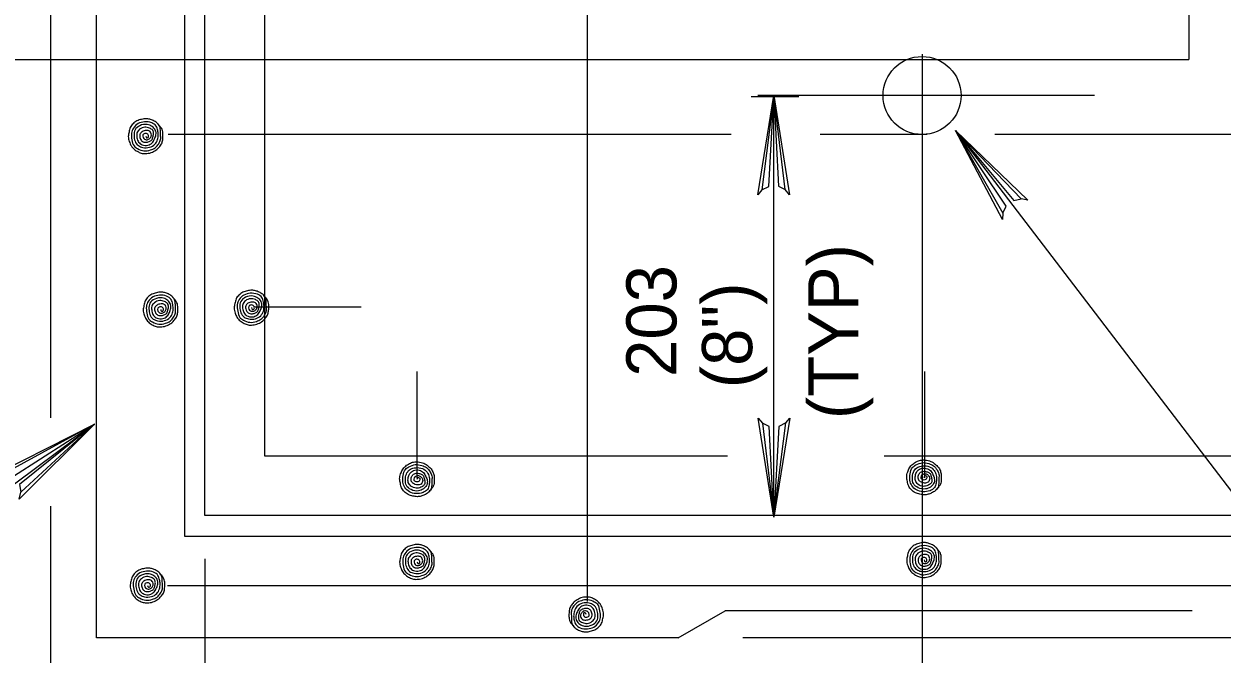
# Model space of a CAD drawing. Extents: x 638455 to 640199, y 298558 to 299152.
# Drawn here: x 638610.5 to 638690.8, y 298927.7 to 298970 of the extents above; entities that cross this region are included whole.
import ezdxf

# ---------------------------------------------------------------- set-up
doc = ezdxf.new("R2010")
doc.units = 0
for name, color, linetype in [('1', 7, 'Continuous'), ('2', 7, 'Continuous'), ('3', 7, 'Continuous')]:
    doc.layers.add(name, color=color, linetype=linetype)

msp = doc.modelspace()

# ---------------------------------------------------------------- linework, layer by layer
at = {"layer": '1'}
msp.add_line((638654.3, 298928.815), (638657.46, 298930.633), dxfattribs=at)
msp.add_lwpolyline([(638609.271, 298939.891), (638609.759, 298939.645), (638615.183, 298943.151), (638609.271, 298939.891), (638608.821, 298939.926), (638615.183, 298943.151), (638610.159, 298939.103), (638610.252, 298938.577), (638615.183, 298943.151), (638610.147, 298938.104), (638610.252, 298938.577)], dxfattribs=at)
at = {"layer": '2'}
for p, q in [((638612.27, 298943.574), (638612.27, 299043.396)), ((638615.328, 298928.815), (638615.328, 299041.293)), ((638648.201, 299038.114), (638648.201, 298931.255)), ((638688.53, 299002.44), (638688.53, 298967.592)), ((638529.296, 298967.592), (638688.53, 298967.592)), ((638670.649, 298967.953), (638670.649, 298905.861)), ((638659.191, 298965.101), (638662.389, 298965.101)), ((638682.211, 298965.179), (638659.644, 298965.179)), ((638660.717, 298936.898), (638660.717, 298965.179)), ((638620.12, 298962.581), (638657.852, 298962.581)), ((638663.822, 298962.581), (638670.987, 298962.581)), ((638672.897, 298962.831), (638713.687, 298909.405)), ((638675.524, 298962.581), (638721.179, 298962.581)), ((638625.946, 298951.012), (638633.07, 298951.012)), ((638636.797, 298946.662), (638636.797, 298939.538)), ((638670.822, 298946.662), (638670.822, 298939.538)), ((638603.045, 298934.093), (638615.183, 298943.151)), ((638657.613, 298940.985), (638626.618, 298940.985)), ((638714.68, 298940.985), (638668.121, 298940.985)), ((638612.27, 298926.637), (638612.27, 298937.652)), ((638622.593, 298934.105), (638622.593, 298879.959)), ((638620.085, 298932.332), (638721.904, 298932.332)), ((638688.753, 298930.633), (638657.46, 298930.633)), ((638654.3, 298928.815), (638615.328, 298928.815)), ((638725.979, 298928.815), (638658.629, 298928.815))]:
    msp.add_line(p, q, dxfattribs=at)
for points in [[(638621.251, 299034.415), (638720.048, 299034.415), (638720.048, 298935.618), (638621.251, 298935.618), (638621.251, 299034.415)], [(638622.593, 299033.135), (638718.705, 299033.135), (638718.705, 298937.023), (638622.593, 298937.023), (638622.593, 299033.135)], [(638626.618, 298940.985), (638626.618, 299029.048)], [(638659.922, 298958.848), (638660.381, 298959.083), (638660.717, 298965.179), (638659.922, 298958.848), (638659.646, 298958.522), (638660.717, 298965.179), (638661.019, 298959.089), (638661.472, 298958.868), (638660.717, 298965.179), (638661.774, 298958.522), (638661.472, 298958.868)], [(638676.07, 298957.296), (638676.293, 298957.761), (638672.897, 298962.831), (638676.07, 298957.296), (638676.041, 298956.87), (638672.897, 298962.831), (638676.799, 298958.146), (638677.296, 298958.244), (638672.897, 298962.831), (638677.743, 298958.152), (638677.296, 298958.244)], [(638661.513, 298943.226), (638661.054, 298942.991), (638660.717, 298936.898), (638661.513, 298943.226), (638661.789, 298943.551), (638660.717, 298936.898), (638660.415, 298942.985), (638659.962, 298943.209), (638660.717, 298936.898), (638659.66, 298943.551), (638659.962, 298943.209)]]:
    msp.add_lwpolyline(points, dxfattribs=at)
msp.add_circle((638670.649, 298965.178), 2.614, dxfattribs=at)
for points in [[(638618.63, 298962.454), (638618.688, 298962.338), (638618.775, 298962.352), (638618.795, 298962.535), (638618.633, 298962.631), (638618.438, 298962.535), (638618.447, 298962.352), (638618.554, 298962.239), (638618.775, 298962.221), (638618.929, 298962.338), (638619.004, 298962.526), (638618.891, 298962.776), (638618.65, 298962.828), (638618.383, 298962.747), (638618.24, 298962.579), (638618.258, 298962.294), (638618.392, 298962.111), (638618.633, 298962.044), (638618.848, 298962.088), (638619.024, 298962.195), (638619.103, 298962.381), (638619.147, 298962.622), (638619.091, 298962.846), (638618.882, 298962.988), (638618.563, 298963.052), (638618.214, 298962.91), (638618.04, 298962.669), (638618.04, 298962.338), (638618.151, 298962.056), (638618.392, 298961.87), (638618.775, 298961.847), (638619.048, 298961.998), (638619.213, 298962.262), (638619.312, 298962.535), (638619.266, 298962.863), (638619.048, 298963.096), (638618.731, 298963.229), (638618.226, 298963.151), (638617.91, 298962.872), (638617.843, 298962.488), (638617.91, 298962.111), (638618.13, 298961.815), (638618.424, 298961.696), (638618.882, 298961.704), (638619.245, 298961.913), (638619.42, 298962.221), (638619.463, 298962.547), (638619.431, 298962.828), (638619.321, 298963.131), (638619.024, 298963.345), (638618.545, 298963.412), (638618.116, 298963.293), (638617.799, 298962.997), (638617.668, 298962.651), (638617.7, 298962.21), (638617.843, 298961.795), (638618.084, 298961.62), (638618.508, 298961.469), (638618.949, 298961.53), (638619.257, 298961.673), (638619.495, 298961.946), (638619.62, 298962.23), (638619.62, 298962.535), (638619.605, 298962.863), (638619.53, 298963.171), (638619.373, 298963.345), (638619.132, 298963.496), (638618.891, 298963.586), (638618.65, 298963.621), (638618.348, 298963.577), (638618.04, 298963.479), (638617.776, 298963.284), (638617.593, 298963.035), (638617.506, 298962.721), (638617.459, 298962.428), (638617.526, 298962.088), (638617.648, 298961.815), (638617.866, 298961.565), (638618.13, 298961.397), (638618.392, 298961.298), (638618.705, 298961.289), (638619.071, 298961.379), (638619.373, 298961.565), (638619.562, 298961.762), (638619.716, 298962.012), (638619.771, 298962.276), (638619.78, 298962.579), (638619.716, 298962.91), (638619.62, 298963.06), (638619.42, 298963.284)], [(638619.629, 298950.83), (638619.687, 298950.714), (638619.774, 298950.728), (638619.794, 298950.911), (638619.632, 298951.007), (638619.437, 298950.911), (638619.446, 298950.728), (638619.553, 298950.615), (638619.774, 298950.597), (638619.928, 298950.714), (638620.004, 298950.902), (638619.89, 298951.152), (638619.649, 298951.204), (638619.382, 298951.123), (638619.24, 298950.955), (638619.257, 298950.67), (638619.391, 298950.487), (638619.632, 298950.42), (638619.847, 298950.464), (638620.024, 298950.571), (638620.102, 298950.757), (638620.146, 298950.998), (638620.091, 298951.222), (638619.882, 298951.364), (638619.562, 298951.428), (638619.214, 298951.286), (638619.039, 298951.045), (638619.039, 298950.714), (638619.15, 298950.432), (638619.391, 298950.246), (638619.774, 298950.223), (638620.047, 298950.374), (638620.213, 298950.638), (638620.311, 298950.911), (638620.265, 298951.239), (638620.047, 298951.472), (638619.731, 298951.605), (638619.225, 298951.527), (638618.909, 298951.248), (638618.842, 298950.864), (638618.909, 298950.487), (638619.13, 298950.191), (638619.423, 298950.072), (638619.882, 298950.08), (638620.245, 298950.289), (638620.419, 298950.597), (638620.462, 298950.923), (638620.43, 298951.204), (638620.32, 298951.507), (638620.024, 298951.721), (638619.545, 298951.788), (638619.115, 298951.669), (638618.798, 298951.373), (638618.668, 298951.027), (638618.7, 298950.586), (638618.842, 298950.171), (638619.083, 298949.996), (638619.507, 298949.845), (638619.948, 298949.906), (638620.256, 298950.049), (638620.495, 298950.322), (638620.619, 298950.606), (638620.619, 298950.911), (638620.605, 298951.239), (638620.529, 298951.547), (638620.372, 298951.721), (638620.132, 298951.872), (638619.89, 298951.962), (638619.649, 298951.997), (638619.347, 298951.953), (638619.039, 298951.855), (638618.775, 298951.66), (638618.592, 298951.411), (638618.505, 298951.097), (638618.459, 298950.804), (638618.526, 298950.464), (638618.647, 298950.191), (638618.865, 298949.941), (638619.13, 298949.773), (638619.391, 298949.674), (638619.704, 298949.665), (638620.07, 298949.755), (638620.372, 298949.941), (638620.561, 298950.138), (638620.715, 298950.388), (638620.77, 298950.652), (638620.779, 298950.955), (638620.715, 298951.286), (638620.619, 298951.436), (638620.419, 298951.66)], [(638625.719, 298950.955), (638625.777, 298950.839), (638625.864, 298950.853), (638625.884, 298951.036), (638625.722, 298951.132), (638625.527, 298951.036), (638625.536, 298950.853), (638625.643, 298950.74), (638625.864, 298950.722), (638626.018, 298950.839), (638626.094, 298951.027), (638625.98, 298951.277), (638625.739, 298951.329), (638625.472, 298951.248), (638625.33, 298951.08), (638625.347, 298950.795), (638625.481, 298950.612), (638625.722, 298950.545), (638625.937, 298950.589), (638626.114, 298950.696), (638626.192, 298950.882), (638626.236, 298951.123), (638626.181, 298951.347), (638625.972, 298951.489), (638625.652, 298951.553), (638625.304, 298951.411), (638625.129, 298951.17), (638625.129, 298950.839), (638625.24, 298950.557), (638625.481, 298950.371), (638625.864, 298950.348), (638626.137, 298950.499), (638626.303, 298950.763), (638626.401, 298951.036), (638626.355, 298951.364), (638626.137, 298951.597), (638625.821, 298951.73), (638625.315, 298951.652), (638624.999, 298951.373), (638624.932, 298950.989), (638624.999, 298950.612), (638625.22, 298950.316), (638625.513, 298950.197), (638625.972, 298950.205), (638626.335, 298950.414), (638626.509, 298950.722), (638626.552, 298951.048), (638626.52, 298951.329), (638626.41, 298951.632), (638626.114, 298951.846), (638625.635, 298951.913), (638625.205, 298951.794), (638624.888, 298951.498), (638624.758, 298951.152), (638624.79, 298950.711), (638624.932, 298950.296), (638625.173, 298950.121), (638625.597, 298949.97), (638626.038, 298950.031), (638626.346, 298950.174), (638626.585, 298950.447), (638626.709, 298950.731), (638626.709, 298951.036), (638626.695, 298951.364), (638626.619, 298951.672), (638626.462, 298951.846), (638626.222, 298951.997), (638625.98, 298952.087), (638625.739, 298952.122), (638625.437, 298952.078), (638625.129, 298951.98), (638624.865, 298951.785), (638624.682, 298951.536), (638624.595, 298951.222), (638624.549, 298950.929), (638624.616, 298950.589), (638624.737, 298950.316), (638624.955, 298950.066), (638625.22, 298949.898), (638625.481, 298949.799), (638625.794, 298949.79), (638626.16, 298949.88), (638626.462, 298950.066), (638626.651, 298950.263), (638626.805, 298950.513), (638626.86, 298950.777), (638626.869, 298951.08), (638626.805, 298951.411), (638626.709, 298951.561), (638626.509, 298951.785)], [(638670.79, 298939.569), (638670.848, 298939.685), (638670.935, 298939.673), (638670.952, 298939.491), (638670.793, 298939.392), (638670.598, 298939.491), (638670.607, 298939.673), (638670.714, 298939.784), (638670.935, 298939.802), (638671.089, 298939.685), (638671.164, 298939.499), (638671.051, 298939.25), (638670.81, 298939.194), (638670.543, 298939.276), (638670.401, 298939.444), (638670.418, 298939.729), (638670.552, 298939.912), (638670.793, 298939.981), (638671.008, 298939.935), (638671.185, 298939.827), (638671.26, 298939.642), (638671.306, 298939.401), (638671.251, 298939.177), (638671.042, 298939.035), (638670.723, 298938.971), (638670.374, 298939.116), (638670.2, 298939.354), (638670.2, 298939.685), (638670.31, 298939.967), (638670.552, 298940.153), (638670.935, 298940.176), (638671.208, 298940.025), (638671.374, 298939.761), (638671.472, 298939.491), (638671.426, 298939.16), (638671.208, 298938.927), (638670.891, 298938.794), (638670.386, 298938.875), (638670.07, 298939.151), (638670.002, 298939.534), (638670.07, 298939.912), (638670.29, 298940.208), (638670.583, 298940.327), (638671.042, 298940.319), (638671.405, 298940.109), (638671.577, 298939.802), (638671.623, 298939.476), (638671.591, 298939.194), (638671.481, 298938.892), (638671.185, 298938.678), (638670.703, 298938.611), (638670.276, 298938.73), (638669.959, 298939.026), (638669.828, 298939.375), (638669.86, 298939.816), (638670.002, 298940.231), (638670.244, 298940.403), (638670.668, 298940.556), (638671.109, 298940.493), (638671.417, 298940.35), (638671.655, 298940.077), (638671.78, 298939.793), (638671.78, 298939.491), (638671.765, 298939.16), (638671.69, 298938.852), (638671.533, 298938.678), (638671.292, 298938.526), (638671.051, 298938.437), (638670.81, 298938.402), (638670.508, 298938.445), (638670.2, 298938.544), (638669.936, 298938.738), (638669.753, 298938.988), (638669.666, 298939.302), (638669.619, 298939.595), (638669.686, 298939.935), (638669.808, 298940.208), (638670.026, 298940.458), (638670.29, 298940.626), (638670.552, 298940.725), (638670.865, 298940.734), (638671.231, 298940.644), (638671.533, 298940.458), (638671.722, 298940.26), (638671.876, 298940.011), (638671.931, 298939.749), (638671.94, 298939.444), (638671.876, 298939.116), (638671.78, 298938.962), (638671.577, 298938.738)], [(638636.812, 298939.444), (638636.87, 298939.56), (638636.957, 298939.548), (638636.975, 298939.366), (638636.815, 298939.267), (638636.62, 298939.366), (638636.629, 298939.548), (638636.736, 298939.659), (638636.957, 298939.677), (638637.111, 298939.56), (638637.186, 298939.374), (638637.073, 298939.125), (638636.832, 298939.069), (638636.565, 298939.151), (638636.423, 298939.319), (638636.44, 298939.604), (638636.574, 298939.787), (638636.815, 298939.856), (638637.03, 298939.81), (638637.207, 298939.702), (638637.282, 298939.517), (638637.329, 298939.276), (638637.273, 298939.052), (638637.064, 298938.91), (638636.745, 298938.846), (638636.396, 298938.991), (638636.222, 298939.229), (638636.222, 298939.56), (638636.333, 298939.842), (638636.574, 298940.028), (638636.957, 298940.051), (638637.23, 298939.9), (638637.396, 298939.636), (638637.494, 298939.366), (638637.448, 298939.035), (638637.23, 298938.802), (638636.913, 298938.669), (638636.408, 298938.75), (638636.092, 298939.026), (638636.025, 298939.409), (638636.092, 298939.787), (638636.312, 298940.083), (638636.605, 298940.202), (638637.064, 298940.194), (638637.427, 298939.984), (638637.599, 298939.677), (638637.645, 298939.351), (638637.614, 298939.069), (638637.503, 298938.767), (638637.207, 298938.553), (638636.725, 298938.486), (638636.298, 298938.605), (638635.981, 298938.901), (638635.851, 298939.25), (638635.883, 298939.691), (638636.025, 298940.106), (638636.266, 298940.278), (638636.69, 298940.431), (638637.131, 298940.368), (638637.439, 298940.225), (638637.677, 298939.952), (638637.802, 298939.668), (638637.802, 298939.366), (638637.788, 298939.035), (638637.712, 298938.727), (638637.555, 298938.553), (638637.314, 298938.401), (638637.073, 298938.312), (638636.832, 298938.277), (638636.53, 298938.32), (638636.222, 298938.419), (638635.958, 298938.613), (638635.775, 298938.863), (638635.688, 298939.177), (638635.642, 298939.47), (638635.708, 298939.81), (638635.83, 298940.083), (638636.048, 298940.333), (638636.312, 298940.501), (638636.574, 298940.6), (638636.888, 298940.609), (638637.253, 298940.519), (638637.555, 298940.333), (638637.744, 298940.135), (638637.898, 298939.886), (638637.953, 298939.624), (638637.962, 298939.319), (638637.898, 298938.991), (638637.802, 298938.837), (638637.599, 298938.613)], [(638636.812, 298933.908), (638636.87, 298933.792), (638636.957, 298933.804), (638636.975, 298933.986), (638636.815, 298934.085), (638636.62, 298933.986), (638636.629, 298933.804), (638636.736, 298933.693), (638636.957, 298933.676), (638637.111, 298933.792), (638637.186, 298933.978), (638637.073, 298934.228), (638636.832, 298934.283), (638636.565, 298934.201), (638636.423, 298934.033), (638636.44, 298933.748), (638636.574, 298933.565), (638636.815, 298933.496), (638637.03, 298933.542), (638637.207, 298933.65), (638637.282, 298933.835), (638637.329, 298934.077), (638637.273, 298934.3), (638637.064, 298934.443), (638636.745, 298934.506), (638636.396, 298934.361), (638636.222, 298934.123), (638636.222, 298933.792), (638636.333, 298933.51), (638636.574, 298933.324), (638636.957, 298933.301), (638637.23, 298933.452), (638637.396, 298933.717), (638637.494, 298933.986), (638637.448, 298934.317), (638637.23, 298934.55), (638636.913, 298934.683), (638636.408, 298934.602), (638636.092, 298934.326), (638636.025, 298933.943), (638636.092, 298933.565), (638636.312, 298933.269), (638636.605, 298933.15), (638637.064, 298933.159), (638637.427, 298933.368), (638637.599, 298933.676), (638637.645, 298934.001), (638637.614, 298934.283), (638637.503, 298934.585), (638637.207, 298934.8), (638636.725, 298934.866), (638636.298, 298934.748), (638635.981, 298934.451), (638635.851, 298934.102), (638635.883, 298933.661), (638636.025, 298933.246), (638636.266, 298933.074), (638636.69, 298932.921), (638637.131, 298932.985), (638637.439, 298933.127), (638637.677, 298933.4), (638637.802, 298933.684), (638637.802, 298933.986), (638637.788, 298934.317), (638637.712, 298934.625), (638637.555, 298934.8), (638637.314, 298934.951), (638637.073, 298935.04), (638636.832, 298935.075), (638636.53, 298935.032), (638636.222, 298934.933), (638635.958, 298934.739), (638635.775, 298934.489), (638635.688, 298934.175), (638635.642, 298933.882), (638635.708, 298933.542), (638635.83, 298933.269), (638636.048, 298933.019), (638636.312, 298932.851), (638636.574, 298932.752), (638636.888, 298932.744), (638637.253, 298932.834), (638637.555, 298933.019), (638637.744, 298933.217), (638637.898, 298933.467), (638637.953, 298933.728), (638637.962, 298934.033), (638637.898, 298934.361), (638637.802, 298934.515), (638637.599, 298934.739)], [(638670.79, 298934.033), (638670.848, 298933.917), (638670.935, 298933.929), (638670.952, 298934.111), (638670.793, 298934.21), (638670.598, 298934.111), (638670.607, 298933.929), (638670.714, 298933.818), (638670.935, 298933.801), (638671.089, 298933.917), (638671.164, 298934.103), (638671.051, 298934.353), (638670.81, 298934.408), (638670.543, 298934.326), (638670.401, 298934.158), (638670.418, 298933.873), (638670.552, 298933.69), (638670.793, 298933.621), (638671.008, 298933.667), (638671.185, 298933.775), (638671.26, 298933.96), (638671.306, 298934.202), (638671.251, 298934.425), (638671.042, 298934.568), (638670.723, 298934.631), (638670.374, 298934.486), (638670.2, 298934.248), (638670.2, 298933.917), (638670.31, 298933.635), (638670.552, 298933.449), (638670.935, 298933.426), (638671.208, 298933.577), (638671.374, 298933.842), (638671.472, 298934.111), (638671.426, 298934.442), (638671.208, 298934.675), (638670.891, 298934.808), (638670.386, 298934.727), (638670.07, 298934.451), (638670.002, 298934.068), (638670.07, 298933.69), (638670.29, 298933.394), (638670.583, 298933.275), (638671.042, 298933.284), (638671.405, 298933.493), (638671.577, 298933.801), (638671.623, 298934.126), (638671.591, 298934.408), (638671.481, 298934.71), (638671.185, 298934.925), (638670.703, 298934.991), (638670.276, 298934.873), (638669.959, 298934.576), (638669.828, 298934.227), (638669.86, 298933.786), (638670.002, 298933.371), (638670.244, 298933.199), (638670.668, 298933.046), (638671.109, 298933.11), (638671.417, 298933.252), (638671.655, 298933.525), (638671.78, 298933.809), (638671.78, 298934.111), (638671.765, 298934.442), (638671.69, 298934.75), (638671.533, 298934.925), (638671.292, 298935.076), (638671.051, 298935.165), (638670.81, 298935.2), (638670.508, 298935.157), (638670.2, 298935.058), (638669.936, 298934.864), (638669.753, 298934.614), (638669.666, 298934.3), (638669.619, 298934.007), (638669.686, 298933.667), (638669.808, 298933.394), (638670.026, 298933.144), (638670.29, 298932.976), (638670.552, 298932.877), (638670.865, 298932.869), (638671.231, 298932.959), (638671.533, 298933.144), (638671.722, 298933.342), (638671.876, 298933.592), (638671.931, 298933.853), (638671.94, 298934.158), (638671.876, 298934.486), (638671.78, 298934.64), (638671.577, 298934.864)], [(638618.752, 298932.325), (638618.81, 298932.208), (638618.9, 298932.223), (638618.917, 298932.406), (638618.755, 298932.505), (638618.56, 298932.406), (638618.569, 298932.223), (638618.676, 298932.113), (638618.9, 298932.092), (638619.051, 298932.208), (638619.126, 298932.397), (638619.016, 298932.647), (638618.775, 298932.699), (638618.505, 298932.621), (638618.363, 298932.45), (638618.38, 298932.165), (638618.516, 298931.982), (638618.755, 298931.915), (638618.969, 298931.959), (638619.15, 298932.066), (638619.225, 298932.255), (638619.269, 298932.496), (638619.216, 298932.717), (638619.007, 298932.862), (638618.685, 298932.923), (638618.336, 298932.78), (638618.162, 298932.54), (638618.162, 298932.208), (638618.276, 298931.93), (638618.516, 298931.741), (638618.9, 298931.718), (638619.17, 298931.872), (638619.335, 298932.133), (638619.434, 298932.406), (638619.39, 298932.737), (638619.17, 298932.969), (638618.853, 298933.103), (638618.351, 298933.022), (638618.034, 298932.746), (638617.968, 298932.362), (638618.034, 298931.982), (638618.252, 298931.688), (638618.545, 298931.567), (638619.007, 298931.575), (638619.367, 298931.784), (638619.541, 298932.092), (638619.585, 298932.421), (638619.553, 298932.699), (638619.443, 298933.004), (638619.15, 298933.219), (638618.668, 298933.286), (638618.238, 298933.164), (638617.921, 298932.871), (638617.793, 298932.522), (638617.822, 298932.081), (638617.968, 298931.666), (638618.209, 298931.491), (638618.633, 298931.34), (638619.074, 298931.401), (638619.382, 298931.546), (638619.617, 298931.817), (638619.742, 298932.104), (638619.742, 298932.406), (638619.728, 298932.737), (638619.652, 298933.045), (638619.495, 298933.219), (638619.257, 298933.37), (638619.016, 298933.457), (638618.775, 298933.495), (638618.47, 298933.448), (638618.162, 298933.352), (638617.901, 298933.155), (638617.718, 298932.906), (638617.628, 298932.595), (638617.584, 298932.298), (638617.651, 298931.959), (638617.77, 298931.688), (638617.988, 298931.439), (638618.252, 298931.267), (638618.516, 298931.172), (638618.827, 298931.16), (638619.193, 298931.25), (638619.495, 298931.439), (638619.684, 298931.633), (638619.841, 298931.883), (638619.893, 298932.147), (638619.902, 298932.45), (638619.841, 298932.78), (638619.742, 298932.931), (638619.541, 298933.155)], [(638648.139, 298930.379), (638648.081, 298930.495), (638647.991, 298930.481), (638647.973, 298930.298), (638648.133, 298930.199), (638648.331, 298930.298), (638648.322, 298930.481), (638648.215, 298930.591), (638647.991, 298930.611), (638647.84, 298930.495), (638647.764, 298930.306), (638647.875, 298930.057), (638648.116, 298930.004), (638648.383, 298930.083), (638648.525, 298930.254), (638648.508, 298930.539), (638648.374, 298930.722), (638648.133, 298930.789), (638647.921, 298930.745), (638647.741, 298930.638), (638647.666, 298930.449), (638647.622, 298930.208), (638647.675, 298929.984), (638647.884, 298929.842), (638648.206, 298929.781), (638648.554, 298929.923), (638648.726, 298930.164), (638648.726, 298930.495), (638648.616, 298930.774), (638648.374, 298930.963), (638647.991, 298930.986), (638647.718, 298930.832), (638647.555, 298930.571), (638647.457, 298930.298), (638647.5, 298929.967), (638647.718, 298929.734), (638648.035, 298929.601), (638648.54, 298929.682), (638648.856, 298929.958), (638648.923, 298930.341), (638648.856, 298930.722), (638648.639, 298931.015), (638648.342, 298931.137), (638647.884, 298931.128), (638647.524, 298930.916), (638647.349, 298930.611), (638647.303, 298930.283), (638647.335, 298930.004), (638647.448, 298929.7), (638647.741, 298929.484), (638648.223, 298929.418), (638648.65, 298929.54), (638648.967, 298929.833), (638649.098, 298930.181), (638649.065, 298930.623), (638648.923, 298931.038), (638648.682, 298931.212), (638648.258, 298931.364), (638647.817, 298931.303), (638647.509, 298931.157), (638647.274, 298930.887), (638647.149, 298930.6), (638647.149, 298930.298), (638647.161, 298929.967), (638647.236, 298929.659), (638647.393, 298929.484), (638647.634, 298929.334), (638647.875, 298929.244), (638648.116, 298929.209), (638648.418, 298929.255), (638648.726, 298929.351), (638648.99, 298929.549), (638649.173, 298929.798), (638649.263, 298930.109), (638649.307, 298930.405), (638649.24, 298930.745), (638649.121, 298931.015), (638648.9, 298931.265), (638648.639, 298931.436), (638648.374, 298931.532), (638648.064, 298931.544), (638647.698, 298931.453), (638647.393, 298931.265), (638647.207, 298931.07), (638647.05, 298930.82), (638646.998, 298930.556), (638646.986, 298930.254), (638647.05, 298929.923), (638647.149, 298929.772), (638647.349, 298929.549)]]:
    msp.add_spline(points, degree=3, dxfattribs=at)

# ---------------------------------------------------------------- texts
at = {"layer": '3'}
for s, p in [('(TYP)', (638666.385, 298943.483)), ('203', (638654.192, 298946.311)), ('(8")', (638659.265, 298945.552))]:
    msp.add_text(s, height=3.36, rotation=90, dxfattribs=at).set_placement(p)

doc.saveas('drawing.dxf')
